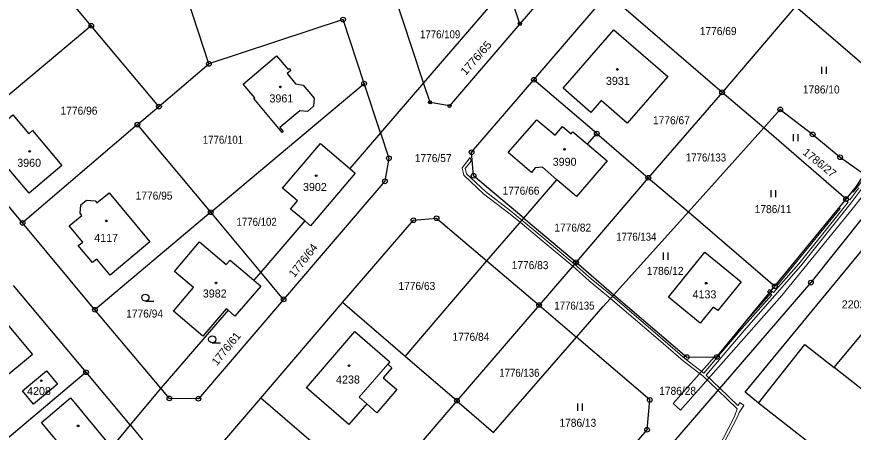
# Model space of a CAD drawing. Extents: x -679733 to -673243, y -1075091 to -1066557.
# Drawn here: x -676904.4 to -676726.8, y -1072594.8 to -1072506.6 of the extents above; entities that cross this region are included whole.
import ezdxf
from ezdxf.enums import TextEntityAlignment as Align

# ---------------------------------------------------------------- set-up
doc = ezdxf.new("R2010")
doc.units = 0
doc.header["$LTSCALE"] = 0.68
for name, color, linetype, lineweight in [('1', 7, 'Continuous', 25), ('13', 7, 'Continuous', 13), ('3', 7, 'Continuous', 25), ('4', 7, 'Continuous', 13), ('5', 7, 'Continuous', 25), ('8', 7, 'Continuous', 25)]:
    doc.layers.add(name, color=color, linetype=linetype, lineweight=lineweight)
doc.layers.add('2', color=7, linetype='Continuous')

msp = doc.modelspace()

# ---------------------------------------------------------------- linework, layer by layer
at = {"layer": '1'}
for p, q in [((-676863.58, -1072516.59), (-676876.54, -1072477.15)), ((-676754.6, -1072522.64), (-676778.94, -1072501.71)), ((-676888.56, -1072508.51), (-676917.69, -1072532.9)), ((-676874.19, -1072525.66), (-676863.58, -1072516.59)), ((-676863.18, -1072548.07), (-676830.64, -1072520.78)), ((-676827.17, -1072531.23), (-676830.64, -1072520.78)), ((-676745.77, -1072530.16), (-676754.6, -1072522.64)), ((-676878.76, -1072529.49), (-676903.14, -1072550.36)), ((-676863.18, -1072548.07), (-676878.76, -1072529.49)), ((-676827.17, -1072531.23), (-676833.69, -1072538.81)), ((-676781.23, -1072531.39), (-676770.28, -1072540.77)), ((-676796.75, -1072549.31), (-676789.7, -1072541.17)), ((-676796.75, -1072549.31), (-676785.62, -1072558.7)), ((-676821.9, -1072578.66), (-676804.57, -1072558.39)), ((-676804.57, -1072558.39), (-676793.47, -1072567.79)), ((-676889.67, -1072582.03), (-676905.1, -1072563.63)), ((-676859.53, -1072568.86), (-676873.78, -1072585.43)), ((-676852.59, -1072587.54), (-676835.19, -1072567.26)), ((-676821.9, -1072578.66), (-676835.19, -1072567.26)), ((-676810.93, -1072588.07), (-676821.9, -1072578.66)), ((-676810.93, -1072588.07), (-676828.32, -1072608.38))]:
    msp.add_line(p, q, dxfattribs=at)
for points in [[(-676818.01, -1072520.59), (-676831.7, -1072479.19), (-676838.85, -1072457.44), (-676846.1, -1072435.49), (-676853.39, -1072413.53)], [(-676758.87, -1072463.05), (-676777.72, -1072485.07), (-676797.57, -1072508.12)], [(-676796.75, -1072549.31), (-676807.39, -1072540.34), (-676807.8, -1072535.36), (-676794.57, -1072519.97), (-676778.94, -1072501.71), (-676763.28, -1072483.53), (-676747.67, -1072465.34)], [(-676888.56, -1072508.51), (-676899.03, -1072496.01), (-676903.54, -1072490.7)], [(-676797.57, -1072508.12), (-676800.27, -1072499.96), (-676818.01, -1072520.59)], [(-676714.91, -1072525.16), (-676739.04, -1072504.4), (-676754.6, -1072522.64)], [(-676830.64, -1072520.78), (-676835.09, -1072507.2), (-676863.58, -1072516.59)], [(-676797.57, -1072508.12), (-676812.51, -1072525.52), (-676816.63, -1072524.76), (-676818.01, -1072520.59), (-676827.17, -1072531.23)], [(-676878.76, -1072529.49), (-676874.19, -1072525.66), (-676888.56, -1072508.51)], [(-676783.18, -1072533.64), (-676781.23, -1072531.39), (-676794.57, -1072519.97)], [(-676754.6, -1072522.64), (-676770.28, -1072540.77), (-676761.78, -1072547.98), (-676745.77, -1072530.16)], [(-676745.77, -1072530.16), (-676742.26, -1072526.25), (-676735.38, -1072531.58), (-676729.55, -1072536.4), (-676724.45, -1072540.03)], [(-676789.7, -1072541.17), (-676792.75, -1072538.54), (-676794.29, -1072538.67), (-676795.11, -1072539.64), (-676800.02, -1072535.4), (-676793.92, -1072528.46), (-676790.06, -1072531.74), (-676788.47, -1072529.87), (-676786.64, -1072531.43), (-676786.28, -1072531), (-676783.18, -1072533.64)], [(-676827.17, -1072531.23), (-676825.37, -1072536.64), (-676826.22, -1072541.52), (-676847.73, -1072566.56)], [(-676761.78, -1072547.98), (-676743.43, -1072563.77), (-676728.29, -1072545.28), (-676745.77, -1072530.16)], [(-676873.78, -1072585.43), (-676887.79, -1072568.76), (-676903.14, -1072550.36), (-676917.69, -1072532.9)], [(-676843.25, -1072549.93), (-676846.23, -1072547.4), (-676844.76, -1072545.68), (-676847.96, -1072542.95), (-676839.86, -1072533.51), (-676833.69, -1072538.81)], [(-676783.18, -1072533.64), (-676779.03, -1072537.17), (-676785.52, -1072544.76), (-676789.7, -1072541.17)], [(-676833.69, -1072538.81), (-676832.53, -1072539.8), (-676842.05, -1072550.96), (-676843.25, -1072549.93), (-676852.57, -1072560.77)], [(-676728.29, -1072545.28), (-676726.09, -1072542.59), (-676724.45, -1072540.03)], [(-676770.28, -1072540.77), (-676785.62, -1072558.7), (-676793.47, -1072567.79), (-676785.53, -1072574.58)], [(-676720.12, -1072543.1), (-676724.33, -1072548.64), (-676735.77, -1072563.02), (-676764.95, -1072596.77), (-676786.33, -1072620.72), (-676806.61, -1072642.84), (-676821.6, -1072659.7), (-676811.77, -1072668.12), (-676801.13, -1072677.24), (-676790.5, -1072686.34), (-676769.24, -1072704.56)], [(-676746.87, -1072588.6), (-676749.72, -1072586.24), (-676718.26, -1072548.14), (-676716.17, -1072545.65), (-676720.12, -1072543.1)], [(-676852.57, -1072560.77), (-676863.18, -1072548.07), (-676887.79, -1072568.76)], [(-676835.19, -1072567.26), (-676820.16, -1072549.77), (-676815.25, -1072549.36), (-676804.57, -1072558.39), (-676796.75, -1072549.31)], [(-676785.62, -1072558.7), (-676777.59, -1072565.57), (-676761.78, -1072547.98)], [(-676859.53, -1072568.86), (-676859.89, -1072568.55), (-676864.87, -1072574.4), (-676871.14, -1072569.04), (-676866.89, -1072564.06), (-676870.91, -1072560.63), (-676865.58, -1072554.33), (-676859.92, -1072559.2), (-676859.08, -1072558.22), (-676854.07, -1072562.51)], [(-676746.87, -1072588.6), (-676737.04, -1072576.11), (-676730.8, -1072581.05), (-676708.58, -1072554.35)], [(-676847.73, -1072566.56), (-676852.57, -1072560.77), (-676854.07, -1072562.51)], [(-676854.07, -1072562.51), (-676852.59, -1072563.78), (-676858.05, -1072570.11), (-676859.53, -1072568.86)], [(-676777.59, -1072565.57), (-676762.11, -1072578.82), (-676755.71, -1072578.76), (-676743.43, -1072563.77)], [(-676847.73, -1072566.56), (-676865.82, -1072587.66), (-676871.98, -1072587.57), (-676873.78, -1072585.43), (-676880.3, -1072593.22)], [(-676785.53, -1072574.58), (-676779.85, -1072568.08), (-676777.59, -1072565.57)], [(-676793.47, -1072567.79), (-676810.93, -1072588.07), (-676803.14, -1072594.78), (-676785.53, -1072574.58)], [(-676784.68, -1072610.67), (-676770.55, -1072594.24), (-676769.96, -1072587.9), (-676785.53, -1072574.58)], [(-676698.62, -1072626.39), (-676689.21, -1072613.81), (-676730.8, -1072581.05)], [(-676880.3, -1072593.22), (-676889.67, -1072582.03), (-676917.41, -1072605.32), (-676903.92, -1072621.47)], [(-676889.48, -1072604.2), (-676899.11, -1072592.68), (-676893, -1072587.47), (-676884.26, -1072597.96)], [(-676892.88, -1072634.48), (-676869.99, -1072607.83), (-676852.59, -1072587.54)], [(-676842.99, -1072603.18), (-676839.32, -1072598.93), (-676852.59, -1072587.54)], [(-676676.04, -1072600.97), (-676677.35, -1072600.85), (-676698.62, -1072626.39), (-676746.87, -1072588.6)], [(-676880.3, -1072593.22), (-676877.73, -1072596.3), (-676877.77, -1072601.45), (-676899.49, -1072626.77)], [(-676880.3, -1072593.22), (-676884.26, -1072597.96), (-676882.64, -1072599.9), (-676888.72, -1072605.1), (-676889.48, -1072604.2)]]:
    msp.add_lwpolyline(points, dxfattribs=at)
for points in [[(-676774.79, -1072529.21), (-676780.31, -1072524.39), (-676782.51, -1072526.91), (-676788.39, -1072521.77), (-676777.57, -1072509.36), (-676766.16, -1072519.31)], [(-676841.24, -1072523.88), (-676841.35, -1072525.57), (-676842.66, -1072526.67), (-676844.31, -1072526.57), (-676848.53, -1072530.09), (-676847.81, -1072530.95), (-676848.03, -1072531.13), (-676854.07, -1072523.97), (-676853.84, -1072523.78), (-676856.29, -1072520.87), (-676849.25, -1072514.88), (-676846.78, -1072517.79), (-676846.55, -1072517.6), (-676846.21, -1072517.98), (-676846.99, -1072518.65), (-676845.19, -1072520.84), (-676843.6, -1072521.09)], [(-676901.84, -1072531.42), (-676901.07, -1072530.77), (-676894.81, -1072538.15), (-676901.79, -1072544.05), (-676908.07, -1072536.66), (-676906.84, -1072535.62), (-676907.53, -1072534.79), (-676908.03, -1072535.2), (-676910.69, -1072532.06), (-676905.23, -1072527.43)], [(-676887.39, -1072558), (-676888.31, -1072558.76), (-676891.32, -1072555.17), (-676890.39, -1072554.42), (-676893.26, -1072550.97), (-676890.59, -1072548.74), (-676890.96, -1072548.3), (-676890.8, -1072546.5), (-676889.59, -1072545.52), (-676887.77, -1072545.66), (-676887.41, -1072546.1), (-676884.8, -1072543.93), (-676876.12, -1072554.37), (-676884.53, -1072561.4)], [(-676766.03, -1072566.07), (-676758.27, -1072556.56), (-676750.54, -1072562.87), (-676755.52, -1072568.96), (-676756.49, -1072568.24), (-676759.27, -1072571.61)], [(-676913.81, -1072576.52), (-676907.1, -1072570.96), (-676901.04, -1072578.28), (-676907.76, -1072583.84)], [(-676832.61, -1072573.4), (-676825.17, -1072579.8), (-676825.61, -1072580.32), (-676824.74, -1072581.07), (-676826.56, -1072583.19), (-676823.66, -1072585.67), (-676827.92, -1072590.66), (-676830.07, -1072588.7), (-676833.85, -1072593.13), (-676842.88, -1072585.36)], [(-676903.19, -1072585.99), (-676898.05, -1072581.7), (-676895.71, -1072584.56), (-676900.84, -1072588.82)]]:
    msp.add_lwpolyline(points, close=True, dxfattribs=at)
at = {"layer": '13'}
for points in [[(-676725.55, -1072542.9), (-676727.48, -1072545.48), (-676728.08, -1072545.03), (-676728.29, -1072545.28), (-676728.46, -1072545.49), (-676727.85, -1072545.95), (-676738.33, -1072559.05), (-676743.67, -1072565.11), (-676744.22, -1072564.74), (-676744.6, -1072565.2), (-676744.07, -1072565.57), (-676750.39, -1072572.75), (-676758.48, -1072582.24), (-676762.47, -1072579.15), (-676768.27, -1072574.14), (-676777.91, -1072565.92), (-676782.45, -1072562.18), (-676785.94, -1072559.08), (-676792.65, -1072553.44), (-676797.13, -1072549.75), (-676799.55, -1072547.76), (-676804.89, -1072543.71), (-676808.9, -1072539.94), (-676809.14, -1072538.8), (-676807.93, -1072537.26), (-676808.08, -1072536.49), (-676809.78, -1072538.66), (-676809.44, -1072540.24), (-676805.27, -1072544.17), (-676799.93, -1072548.24), (-676797.52, -1072550.21), (-676793.03, -1072553.9), (-676786.34, -1072559.53), (-676782.83, -1072562.64), (-676778.31, -1072566.37), (-676768.67, -1072574.6), (-676762.85, -1072579.61), (-676758.64, -1072582.88), (-676755.52, -1072585.86), (-676751.38, -1072589.82), (-676751.98, -1072591.4), (-676755.67, -1072598.53)], [(-676724.01, -1072540.34), (-676726.78, -1072543.81), (-676726.96, -1072543.66), (-676728.29, -1072545.28), (-676729.77, -1072547.09), (-676729.55, -1072547.27), (-676742.83, -1072563.56), (-676743.07, -1072563.33), (-676743.43, -1072563.77), (-676744.37, -1072564.92), (-676744.15, -1072565.12), (-676749.09, -1072570.68), (-676755.71, -1072578.76), (-676756.26, -1072578.77), (-676765.01, -1072588.69), (-676763.44, -1072590.06), (-676751.63, -1072576.68), (-676741.91, -1072565.75), (-676727.27, -1072547.78), (-676722.3, -1072541.56)], [(-676722.62, -1072623.77), (-676736.21, -1072612.82), (-676743.84, -1072607.17), (-676754.34, -1072599.07), (-676755.08, -1072598.69), (-676751.44, -1072591.64), (-676751.02, -1072590.55), (-676750, -1072589.06), (-676750.8, -1072588.45), (-676751.25, -1072589.11), (-676755.13, -1072585.41), (-676758.03, -1072582.63), (-676749.93, -1072573.15), (-676743.39, -1072565.71), (-676737.87, -1072559.43), (-676727.18, -1072546.08), (-676725.05, -1072543.24)]]:
    msp.add_lwpolyline(points, dxfattribs=at)
for points in [[(-676728.46, -1072545.49), (-676728.29, -1072545.28), (-676728.58, -1072545.03), (-676728.77, -1072545.27)], [(-676728.29, -1072545.28), (-676728.08, -1072545.03), (-676728.39, -1072544.8), (-676728.58, -1072545.03)], [(-676744.6, -1072565.2), (-676744.22, -1072564.74), (-676744.57, -1072564.5), (-676744.95, -1072564.97)]]:
    msp.add_lwpolyline(points, close=True, dxfattribs=at)
at = {"layer": '3'}
for p, q in [((-676733.411, -1072518.74), (-676733.411, -1072517.24)), ((-676732.41, -1072518.74), (-676732.41, -1072517.24)), ((-676739.431, -1072532.99), (-676739.431, -1072531.49)), ((-676738.43, -1072532.99), (-676738.43, -1072531.49)), ((-676744.181, -1072544.86), (-676744.181, -1072543.36)), ((-676743.18, -1072544.86), (-676743.18, -1072543.36)), ((-676767.071, -1072558.15), (-676767.071, -1072556.65)), ((-676766.07, -1072558.15), (-676766.07, -1072556.65)), ((-676877.063, -1072566.94), (-676875.313, -1072566.94)), ((-676862.893, -1072575.79), (-676861.143, -1072575.79)), ((-676785.281, -1072590.19), (-676785.281, -1072588.69)), ((-676784.28, -1072590.19), (-676784.28, -1072588.69))]:
    msp.add_line(p, q, dxfattribs=at)
for centre in [(-676877.0629, -1072566.1898), (-676862.8929, -1072575.0398)]:
    msp.add_circle(centre, 0.75, dxfattribs=at)
at = {"layer": '4'}
for p, q in [((-676831.65, -1072587.34), (-676825.61, -1072580.32)), ((-676830.07, -1072588.7), (-676831.65, -1072587.34))]:
    msp.add_line(p, q, dxfattribs=at)
at = {"layer": '5'}
for centre in [(-676776.8568, -1072517.7792), (-676848.4168, -1072521.4792), (-676901.6368, -1072535.1592), (-676788.0868, -1072534.7192), (-676840.8268, -1072540.3092), (-676885.3768, -1072549.9192), (-676862.0868, -1072563.0592), (-676757.9868, -1072563.1292), (-676833.8268, -1072580.6392), (-676899.1868, -1072583.8192), (-676891.3568, -1072593.3992)]:
    msp.add_circle(centre, 0.175, dxfattribs=at)
at = {"layer": '8'}
for centre, radius in [((-676835.09, -1072507.1999), 0.5), ((-676888.56, -1072508.5099), 0.5), ((-676888.56, -1072508.5099), 0.0303), ((-676835.09, -1072507.1999), 0.0303), ((-676797.57, -1072508.1199), 0.335), ((-676797.57, -1072508.1199), 0.0203), ((-676863.58, -1072516.5899), 0.5), ((-676863.58, -1072516.5899), 0.0303), ((-676830.64, -1072520.7799), 0.5), ((-676830.64, -1072520.7799), 0.0303), ((-676794.57, -1072519.9699), 0.5), ((-676794.57, -1072519.9699), 0.0303), ((-676754.6, -1072522.6399), 0.5), ((-676754.6, -1072522.6399), 0.0303), ((-676816.63, -1072524.7599), 0.335), ((-676874.19, -1072525.6599), 0.5), ((-676874.19, -1072525.6599), 0.0303), ((-676816.63, -1072524.7599), 0.0203), ((-676812.51, -1072525.5199), 0.335), ((-676812.51, -1072525.5199), 0.0203), ((-676742.26, -1072526.2499), 0.5), ((-676742.26, -1072526.2499), 0.0303), ((-676878.76, -1072529.4899), 0.5), ((-676878.76, -1072529.4899), 0.0303), ((-676781.23, -1072531.3899), 0.5), ((-676781.23, -1072531.3899), 0.0303), ((-676735.38, -1072531.5799), 0.5), ((-676735.38, -1072531.5799), 0.0303), ((-676807.8, -1072535.3599), 0.5), ((-676825.37, -1072536.6399), 0.5), ((-676825.37, -1072536.6399), 0.0303), ((-676807.8, -1072535.3599), 0.0303), ((-676729.55, -1072536.3999), 0.5), ((-676729.55, -1072536.3999), 0.0303), ((-676807.39, -1072540.3399), 0.5), ((-676807.39, -1072540.3399), 0.0303), ((-676770.28, -1072540.7699), 0.5), ((-676826.22, -1072541.5199), 0.5), ((-676826.22, -1072541.5199), 0.0303), ((-676770.28, -1072540.7699), 0.0303), ((-676728.29, -1072545.2799), 0.5), ((-676728.29, -1072545.2799), 0.0303), ((-676863.18, -1072548.0699), 0.5), ((-676863.18, -1072548.0699), 0.0303), ((-676820.16, -1072549.7699), 0.5), ((-676815.25, -1072549.3599), 0.5), ((-676815.25, -1072549.3599), 0.0303), ((-676903.14, -1072550.3599), 0.5), ((-676903.14, -1072550.3599), 0.0303), ((-676820.16, -1072549.7699), 0.0303), ((-676785.62, -1072558.6999), 0.5), ((-676785.62, -1072558.6999), 0.0303), ((-676743.43, -1072563.7699), 0.5), ((-676735.77, -1072563.0199), 0.5), ((-676735.77, -1072563.0199), 0.0303), ((-676743.43, -1072563.7699), 0.0303), ((-676847.73, -1072566.5599), 0.5), ((-676847.73, -1072566.5599), 0.0303), ((-676887.79, -1072568.7599), 0.5), ((-676887.79, -1072568.7599), 0.0303), ((-676793.47, -1072567.7899), 0.5), ((-676793.47, -1072567.7899), 0.0303), ((-676762.11, -1072578.8199), 0.5), ((-676762.11, -1072578.8199), 0.0303), ((-676755.71, -1072578.7599), 0.5), ((-676755.71, -1072578.7599), 0.0303), ((-676889.67, -1072582.0299), 0.5), ((-676889.67, -1072582.0299), 0.0303), ((-676871.98, -1072587.5699), 0.5), ((-676871.98, -1072587.5699), 0.0303), ((-676865.82, -1072587.6599), 0.5), ((-676865.82, -1072587.6599), 0.0303), ((-676810.93, -1072588.0699), 0.5), ((-676810.93, -1072588.0699), 0.0303), ((-676769.96, -1072587.8999), 0.5), ((-676769.96, -1072587.8999), 0.0303), ((-676770.55, -1072594.2399), 0.5), ((-676770.55, -1072594.2399), 0.0303)]:
    msp.add_circle(centre, radius, dxfattribs=at)

# ---------------------------------------------------------------- texts
at = {"layer": '2'}
for s, width, p in [('1776/109', 0.9, (-676818.75, -1072511.18)), ('1786/10', 0.95, (-676737.46, -1072522.88)), ('1776/96', 0.95, (-676895.07, -1072527.38)), ('1776/67', 0.95, (-676769.28, -1072529.41)), ('1776/101', 0.9, (-676864.87, -1072533.54)), ('1776/57', 0.95, (-676819.87, -1072537.44)), ('1776/133', 0.9, (-676762.3, -1072537.31)), ('1776/66', 0.95, (-676801.21, -1072544.35)), ('1786/11', 0.95, (-676747.69, -1072548.269)), ('1776/102', 0.9, (-676857.72, -1072550.96)), ('1776/82', 0.95, (-676790.23, -1072552.19)), ('1776/134', 0.9, (-676777.09, -1072554.12)), ('1776/83', 0.95, (-676799.29, -1072560.15)), ('1786/12', 0.95, (-676770.61, -1072561.37)), ('1776/63', 0.95, (-676823.33, -1072564.57)), ('1776/135', 0.9, (-676790.24, -1072568.739)), ('1776/94', 0.95, (-676881.14, -1072570.43)), ('1776/84', 0.95, (-676811.84, -1072575.36)), ('1776/136', 0.9, (-676801.93, -1072582.989)), ('1786/28', 0.95, (-676767.96, -1072586.82)), ('1786/13', 0.95, (-676789.15, -1072593.6))]:
    msp.add_text(s, height=1.7, dxfattribs=dict(at, width=width)).set_placement(p)
at = {"layer": '2', "width": 0.95}
for s, p in [('1776/69', (-676755.44, -1072510.489)), ('1776/95', (-676875.23, -1072545.4))]:
    msp.add_text(s, height=1.7, dxfattribs=at).set_placement(p, align=Align.CENTER)
at = {"layer": '2', "width": 1.05}
msp.add_text('1776/65', height=1.7, rotation=49, dxfattribs=at).set_placement((-676809.058, -1072519.167))
at = {"layer": '2'}
for s, p in [('3931', (-676779.28, -1072521.06)), ('3961', (-676850.73, -1072524.779)), ('3960', (-676904.29, -1072538.44)), ('3990', (-676790.58, -1072538.22)), ('3902', (-676843.61, -1072543.57)), ('3982', (-676864.88, -1072566.17)), ('2202', (-676729.21, -1072568.479))]:
    msp.add_text(s, height=1.7, dxfattribs=at).set_placement(p)
for s, rotation, p in [('1786/27', 321, (-676737.634, -1072535.66)), ('1776/64', 52, (-676845.44, -1072562.063)), ('1776/61', 51, (-676861.859, -1072580.744))]:
    msp.add_text(s, height=1.7, rotation=rotation, dxfattribs=at).set_placement(p)
for s, p in [('4117', (-676885.41, -1072554.37)), ('4133', (-676758.36, -1072566.35)), ('4238', (-676834.05, -1072584.42)), ('4208', (-676899.67, -1072586.86))]:
    msp.add_text(s, height=1.7, dxfattribs=at).set_placement(p, align=Align.CENTER)

doc.saveas('drawing.dxf')
